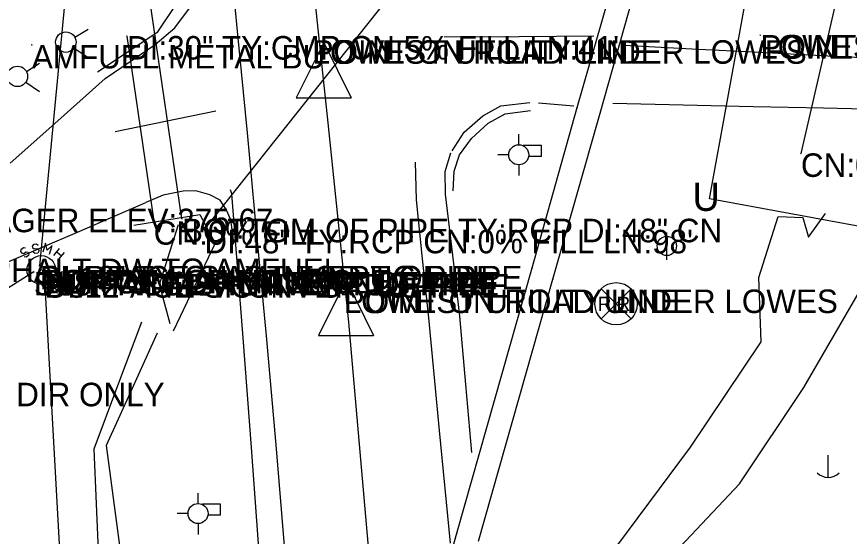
# Model space of a CAD drawing. Extents: x 929765 to 934279, y 1533086 to 1541189.
# Drawn here: x 931934.2 to 932111.4, y 1537427.6 to 1537538.1 of the extents above; entities that cross this region are included whole.
import ezdxf

# ---------------------------------------------------------------- set-up
doc = ezdxf.new("R2010")
doc.units = 0
for name, color, linetype in [('Default', 7, 'Continuous'), ('S_CAL_CORNER', 7, 'Continuous'), ('S_CROSS_DRAIN', 7, 'Continuous'), ('S_CROSS_DRAIN_ANNOT', 7, 'Continuous'), ('S_CURB', 7, 'Continuous'), ('S_DITCHLINE', 7, 'Continuous'), ('S_DRG_PT_SYM', 7, 'Continuous'), ('S_DRIVEWAY', 7, 'Continuous'), ('S_EDGE_CONCRETE', 7, 'Continuous'), ('S_EDGE_PAVEMENT', 7, 'Continuous'), ('S_ELECTRIC_UTILITIES_ANNOT', 7, 'Continuous'), ('S_HEADWALL', 7, 'Continuous'), ('S_HIST_HIGH_WATER_ANNOT', 7, 'Continuous'), ('S_MANHOLE_ANNOT', 7, 'Continuous'), ('S_MSC_PT_SYM', 7, 'Continuous'), ('S_PAVEMENT_CROWN', 7, 'Continuous'), ('S_RAILROAD', 7, 'Continuous'), ('S_SANITARY_SEWER', 7, 'Continuous'), ('S_SANITARY_SEWER_ANNOT', 7, 'Continuous'), ('S_SHOULDER', 7, 'Continuous'), ('S_STORM_SEWER', 7, 'Continuous'), ('S_STORM_SEWER_ANNOT', 7, 'Continuous'), ('S_SURVEY_TEXT_ANNOT', 7, 'Continuous'), ('S_UNDERGROUND_CABLE', 7, 'Continuous'), ('S_UTILITY_POLE', 7, 'Continuous'), ('S_UTL_PT_SYM', 7, 'Continuous'), ('S_WATER_UTILITIES', 7, 'Continuous')]:
    doc.layers.add(name, color=color, linetype=linetype)

msp = doc.modelspace()

# ---------------------------------------------------------------- linework, layer by layer
at = {"layer": 'S_CAL_CORNER'}
for p, q in [((931999.53, 1537532.6), (931993.65, 1537520.78)), ((931999.53, 1537532.6), (932005.34, 1537520.78)), ((931993.65, 1537520.78), (932005.34, 1537520.78)), ((932004.31, 1537482.11), (931998.43, 1537470.29)), ((932004.31, 1537482.11), (932010.12, 1537470.29)), ((931998.43, 1537470.29), (932010.12, 1537470.29))]:
    msp.add_line(p, q, dxfattribs=at)
at = {"layer": 'S_CROSS_DRAIN'}
for p, q in [((931974.13, 1537492.75), (932035.18, 1537569.61)), ((932110.43, 1537549.57), (932101.07, 1537509)), ((931957.67, 1537533.94), (931963.36, 1537494.58))]:
    msp.add_line(p, q, dxfattribs=at)
at = {"layer": 'S_CURB'}
for points in [[(931951.42, 1537526.31), (931964.23, 1537534.86), (931972.76, 1537547.6), (931973.29, 1537552.29), (931973.36, 1537555.14), (931972.31, 1537562.3), (931970.08, 1537579.27), (931967.84, 1537596.25), (931965.61, 1537613.23), (931963.38, 1537630.2), (931960.78, 1537646.56), (931958.18, 1537662.91), (931955.58, 1537679.26), (931952.98, 1537695.61), (931950.14, 1537711.26), (931947.3, 1537726.92), (931944.46, 1537742.57), (931941.62, 1537758.23)], [(932027.11, 1537501.01), (932027.27, 1537505.24), (932028.44, 1537508.67), (932030.95, 1537512.17), (932034.53, 1537515.45), (932038.11, 1537517.37), (932043.52, 1537518.14)], [(931980.38, 1537490.02), (931979.79, 1537494.9), (931978.77, 1537497.08), (931977.48, 1537499.06), (931975.31, 1537500.19), (931972.33, 1537501.01), (931969.61, 1537500.99), (931965.38, 1537500.09), (931961.69, 1537498.53)]]:
    msp.add_lwpolyline(points, dxfattribs=at)
at = {"layer": 'S_DITCHLINE'}
for points in [[(932085.78, 1537301.84), (932081.18, 1537319.05), (932076.57, 1537336.26), (932071.43, 1537351.35), (932066.29, 1537366.45), (932053.86, 1537378.37), (932049.5, 1537380.42), (932059.98, 1537382.88), (932059.48, 1537390.45), (932058.32, 1537398.79), (932058.33, 1537404.72), (932057.44, 1537410.6), (932057.14, 1537417.22), (932059.87, 1537422.73), (932068.73, 1537434.65), (932077.6, 1537446.56), (932085.12, 1537457.75), (932092.64, 1537468.94), (932092.11, 1537482.59), (932096.23, 1537495.57), (932101.45, 1537495.39), (932102.69, 1537491.18), (932106.29, 1537496.21)], [(932126.62, 1537258.44), (932108.91, 1537270.62), (932105.45, 1537284.68), (932101.98, 1537298.75), (932094.32, 1537317.71), (932086.66, 1537336.67), (932081.51, 1537352.24), (932076.37, 1537367.8), (932068.43, 1537383.73), (932067.92, 1537400.37), (932067.42, 1537417), (932077.7, 1537427.87), (932087.98, 1537438.73), (932101.66, 1537459.25), (932108.63, 1537471.21), (932115.61, 1537483.17), (932113.54, 1537495.88)], [(931960.73, 1537473.11), (931955.67, 1537459.62), (931950.61, 1537446.13), (931951.63, 1537422.85), (931946.42, 1537416.45), (931944.44, 1537403.55), (931942.46, 1537390.65), (931930.06, 1537380.86), (931917.67, 1537371.06), (931905.8, 1537349.22), (931891.3, 1537336.47)], [(931964.13, 1537470.78), (931958.69, 1537458.85), (931953.25, 1537446.93), (931956.11, 1537425.64), (931962.3, 1537423.93), (931964.69, 1537424.11), (931966.9, 1537401.27), (931969.1, 1537378.44), (931958.88, 1537373.67), (931949.96, 1537376.9), (931937.32, 1537372.75), (931924.68, 1537368.59), (931916.88, 1537353.63), (931909.08, 1537338.66), (931901.6, 1537326.5), (931894.11, 1537314.34), (931873.82, 1537300.85), (931853.53, 1537287.36), (931835.12, 1537272.97), (931824.41, 1537264.81), (931813.7, 1537256.65), (931802.99, 1537248.49), (931792.29, 1537240.33), (931772.04, 1537229.23)]]:
    msp.add_lwpolyline(points, dxfattribs=at)
at = {"layer": 'S_DRG_PT_SYM'}
for points in [[(931957.67, 1537533.94), (931957.67, 1537533.99), (931957.67, 1537533.94), (931957.62, 1537533.94), (931957.67, 1537533.94), (931957.67, 1537533.89), (931957.67, 1537533.94), (931957.72, 1537533.94)], [(932101.07, 1537509), (932101.07, 1537509.05), (932101.07, 1537509), (932101.02, 1537509), (932101.07, 1537509), (932101.07, 1537508.95), (932101.07, 1537509), (932101.12, 1537509)], [(931963.36, 1537494.58), (931963.36, 1537494.63), (931963.36, 1537494.58), (931963.31, 1537494.58), (931963.36, 1537494.58), (931963.36, 1537494.53), (931963.36, 1537494.58), (931963.41, 1537494.58)], [(931974.13, 1537492.75), (931974.13, 1537492.8), (931974.13, 1537492.75), (931974.08, 1537492.75), (931974.13, 1537492.75), (931974.13, 1537492.7), (931974.13, 1537492.75), (931974.18, 1537492.75)]]:
    msp.add_lwpolyline(points, dxfattribs=at)
at = {"layer": 'S_DRIVEWAY'}
for points in [[(931932.85, 1537506.93), (931942.95, 1537515.91), (931953.05, 1537524.89)], [(931932.55, 1537485.99), (931947.12, 1537492.26), (931961.69, 1537498.53)]]:
    msp.add_lwpolyline(points, dxfattribs=at)
at = {"layer": 'S_EDGE_CONCRETE'}
for points in [[(932026.88, 1537509.56), (932029.42, 1537513.53), (932033.42, 1537516.97), (932037.22, 1537519.12), (932043.39, 1537519.83)], [(931966.87, 1537472.8), (931964.6, 1537481.12), (931968.6, 1537493.89)]]:
    msp.add_lwpolyline(points, dxfattribs=at)
at = {"layer": 'S_EDGE_PAVEMENT'}
for points in [[(931999.26, 1537333.05), (931997.86, 1537345.98), (931996.59, 1537361.76), (931995.32, 1537377.53), (931993.34, 1537400.7), (931991.36, 1537423.88), (931989.38, 1537447.05), (931987.39, 1537470.22), (931985.33, 1537491.8), (931983.28, 1537513.38), (931981.22, 1537534.96), (931979.16, 1537556.54)], [(931953.05, 1537524.89), (931963.67, 1537532.14), (931967.87, 1537535.71), (931972.01, 1537541.26)], [(932045.23, 1537519.74), (932052.76, 1537519.09)], [(932061.04, 1537519.67), (932075.98, 1537519.33), (932090.91, 1537518.99), (932105.85, 1537518.66), (932120.78, 1537518.32), (932134.72, 1537517.68), (932148.65, 1537517.03), (932162.59, 1537516.39), (932176.52, 1537515.74), (932190.49, 1537514.88), (932204.46, 1537514.03), (932218.44, 1537513.17), (932232.41, 1537512.32), (932253.88, 1537511.23), (932275.34, 1537510.15), (932296.81, 1537509.07), (932318.28, 1537507.98), (932331.24, 1537507.41), (932344.21, 1537506.84), (932357.18, 1537506.27), (932370.14, 1537505.7)], [(932026.51, 1537426.11), (932024.2, 1537450.08), (932021.89, 1537474.04), (932020.58, 1537486.58), (932019.27, 1537499.11), (932019.09, 1537507.16)]]:
    msp.add_lwpolyline(points, dxfattribs=at)
at = {"layer": 'S_HEADWALL'}
msp.add_lwpolyline([(931959.16, 1537493.75), (931973.16, 1537495.99), (931976.41, 1537489.94), (931967.47, 1537471.24)], dxfattribs=at)
at = {"layer": 'S_MSC_PT_SYM'}
for points in [[(932092.43, 1537534.14), (932092.43, 1537534.19), (932092.43, 1537534.14), (932092.38, 1537534.14), (932092.43, 1537534.14), (932092.43, 1537534.09), (932092.43, 1537534.14), (932092.48, 1537534.14)], [(931997.16, 1537533.05), (931997.16, 1537533.1), (931997.16, 1537533.05), (931997.11, 1537533.05), (931997.16, 1537533.05), (931997.16, 1537533), (931997.16, 1537533.05), (931997.21, 1537533.05)], [(931937.44, 1537532.05), (931937.44, 1537532.1), (931937.44, 1537532.05), (931937.39, 1537532.05), (931937.44, 1537532.05), (931937.44, 1537532), (931937.44, 1537532.05), (931937.49, 1537532.05)], [(932053.49, 1537518.73), (932053.49, 1537518.78), (932053.49, 1537518.73), (932053.44, 1537518.73), (932053.49, 1537518.73), (932053.49, 1537518.68), (932053.49, 1537518.73), (932053.54, 1537518.73)], [(932058.32, 1537517.56), (932058.32, 1537517.61), (932058.32, 1537517.56), (932058.27, 1537517.56), (932058.32, 1537517.56), (932058.32, 1537517.51), (932058.32, 1537517.56), (932058.37, 1537517.56)], [(931939.08, 1537485.09), (931939.08, 1537485.14), (931939.08, 1537485.09), (931939.03, 1537485.09), (931939.08, 1537485.09), (931939.08, 1537485.04), (931939.08, 1537485.09), (931939.13, 1537485.09)], [(932043.89, 1537484.68), (932043.89, 1537484.73), (932043.89, 1537484.68), (932043.84, 1537484.68), (932043.89, 1537484.68), (932043.89, 1537484.63), (932043.89, 1537484.68), (932043.94, 1537484.68)], [(931937.87, 1537483.79), (931937.87, 1537483.84), (931937.87, 1537483.79), (931937.82, 1537483.79), (931937.87, 1537483.79), (931937.87, 1537483.74), (931937.87, 1537483.79), (931937.92, 1537483.79)], [(931940.09, 1537483.33), (931940.09, 1537483.38), (931940.09, 1537483.33), (931940.04, 1537483.33), (931940.09, 1537483.33), (931940.09, 1537483.28), (931940.09, 1537483.33), (931940.14, 1537483.33)], [(932048.31, 1537482.23), (932048.31, 1537482.28), (932048.31, 1537482.23), (932048.26, 1537482.23), (932048.31, 1537482.23), (932048.31, 1537482.18), (932048.31, 1537482.23), (932048.36, 1537482.23)], [(932003.8, 1537480.06), (932003.8, 1537480.11), (932003.8, 1537480.06), (932003.75, 1537480.06), (932003.8, 1537480.06), (932003.8, 1537480.01), (932003.8, 1537480.06), (932003.85, 1537480.06)], [(932027.87, 1537428.26), (932027.87, 1537428.31), (932027.87, 1537428.26), (932027.82, 1537428.26), (932027.87, 1537428.26), (932027.87, 1537428.21), (932027.87, 1537428.26), (932027.92, 1537428.26)]]:
    msp.add_lwpolyline(points, dxfattribs=at)
at = {"layer": 'S_PAVEMENT_CROWN'}
for points in [[(932013.1, 1537379.23), (932011.05, 1537402.7), (932008.99, 1537426.17), (932006.94, 1537449.63), (932004.88, 1537473.1), (932002.67, 1537494.31), (932000.45, 1537515.52), (931998.24, 1537536.73), (931996.02, 1537557.94)], [(932025.17, 1537533.78), (932041.09, 1537533.87), (932057.01, 1537533.96)], [(932063.43, 1537531.97), (932077.89, 1537531.23), (932092.36, 1537530.49), (932106.82, 1537529.75), (932121.29, 1537529.01), (932135.07, 1537528.19), (932148.84, 1537527.38), (932162.62, 1537526.56), (932176.4, 1537525.75), (932191.1, 1537524.87), (932205.8, 1537523.99), (932220.5, 1537523.11), (932235.2, 1537522.24), (932255.86, 1537521.16), (932276.51, 1537520.09), (932297.17, 1537519.01), (932317.82, 1537517.94), (932331.13, 1537517.43), (932344.43, 1537516.92), (932357.74, 1537516.42), (932371.04, 1537515.91)], [(931976.59, 1537517.96), (931955.18, 1537513.56)]]:
    msp.add_lwpolyline(points, dxfattribs=at)
at = {"layer": 'S_RAILROAD'}
for p, q in [((932053.49, 1537518.73), (932069.38, 1537574.33)), ((932058.32, 1537517.56), (932073.74, 1537571.91)), ((932043.89, 1537484.68), (932053.49, 1537518.73)), ((932048.31, 1537482.23), (932058.32, 1537517.56)), ((932041.03, 1537510.81), (932041.03, 1537513.06)), ((932045.84, 1537510.65), (932041.96, 1537510.65)), ((932045.84, 1537508.33), (932045.84, 1537510.65)), ((932038.94, 1537508.68), (932036.61, 1537508.68)), ((932045.84, 1537508.33), (932043.12, 1537508.33)), ((932041.11, 1537504.26), (932041.11, 1537506.58)), ((932027.87, 1537428.26), (932043.89, 1537484.68)), ((932032.49, 1537426.55), (932048.31, 1537482.23)), ((931972.79, 1537434.55), (931972.79, 1537436.8)), ((931977.6, 1537434.4), (931973.72, 1537434.4)), ((931977.6, 1537432.07), (931977.6, 1537434.4)), ((931970.7, 1537432.42), (931968.38, 1537432.42)), ((931977.6, 1537432.07), (931974.89, 1537432.07)), ((931972.87, 1537428), (931972.87, 1537430.33)), ((932013.4, 1537376.69), (932027.87, 1537428.26))]:
    msp.add_line(p, q, dxfattribs=at)
for points in [[(932058.57, 1537480.2), (932061.75, 1537477.02), (932058.57, 1537473.83)], [(932064.93, 1537480.2), (932061.75, 1537477.02), (932064.93, 1537473.83)]]:
    msp.add_lwpolyline(points, dxfattribs=at)
for centre, radius in [((932041.03, 1537508.7), 2.13), ((932061.75, 1537477.02), 4.5), ((931972.79, 1537432.44), 2.13)]:
    msp.add_circle(centre, radius, dxfattribs=at)
at = {"layer": 'S_SANITARY_SEWER'}
for p, q in [((931946.28, 1537561.11), (931939.08, 1537485.09)), ((931935.11, 1537488.52), (931935.03, 1537488.14)), ((931935.03, 1537488.14), (931935.23, 1537487.87)), ((931935.65, 1537488.91), (931935.11, 1537488.52)), ((931936.08, 1537488.83), (931935.65, 1537488.91)), ((931935.65, 1537487.75), (931936.2, 1537488.1)), ((931936.2, 1537488.1), (931936.66, 1537488.02)), ((931936.66, 1537488.02), (931936.82, 1537487.75)), ((931942.09, 1537487.28), (931943.33, 1537488.76)), ((931942.74, 1537488.06), (931943.71, 1537487.25)), ((931944.29, 1537487.94), (931943.05, 1537486.47)), ((931935.23, 1537487.87), (931935.65, 1537487.75)), ((931936.2, 1537486.94), (931935.81, 1537487.01)), ((931936.74, 1537487.32), (931936.2, 1537486.94)), ((931936.82, 1537487.75), (931936.74, 1537487.32)), ((931937.87, 1537483.79), (931900.29, 1537460.24)), ((931950.77, 1537292.06), (931940.09, 1537483.33))]:
    msp.add_line(p, q, dxfattribs=at)
for points in [[(931938.75, 1537489.45), (931938.4, 1537489.73), (931937.75, 1537489.65), (931937.51, 1537489.3), (931937.55, 1537488.99), (931937.9, 1537488.68), (931938.52, 1537488.8), (931938.91, 1537488.49), (931938.95, 1537488.18), (931938.68, 1537487.79), (931938.06, 1537487.71), (931937.71, 1537487.98)], [(931941.19, 1537487.59), (931941.74, 1537489.45), (931940.69, 1537488.45), (931940.3, 1537489.88), (931939.76, 1537488.02)]]:
    msp.add_lwpolyline(points, dxfattribs=at)
msp.add_circle((931939.44, 1537484.22), 3.05, dxfattribs=at)
at = {"layer": 'S_SHOULDER'}
for points in [[(932031.07, 1537445.4), (932029.8, 1537459.9), (932028.52, 1537474.39), (932026.98, 1537487.36), (932025.44, 1537500.33), (932025.4, 1537505.13), (932026.6, 1537509.09)], [(931992.49, 1537324.27), (931991.71, 1537337.31), (931990.93, 1537350.35), (931990.15, 1537363.39), (931989.37, 1537376.43), (931987.64, 1537399.77), (931985.9, 1537423.12), (931984.16, 1537446.46), (931982.42, 1537469.81), (931981.22, 1537485.1), (931980.01, 1537500.39), (931979.72, 1537501.28)]]:
    msp.add_lwpolyline(points, dxfattribs=at)
at = {"layer": 'S_STORM_SEWER'}
msp.add_line((931969.37, 1537495.1), (931941.79, 1537683.51), dxfattribs=at)
at = {"layer": 'S_UNDERGROUND_CABLE'}
for p, q in [((932081.62, 1537499.31), (932094.03, 1537567.82)), ((932135.91, 1537489.36), (932081.62, 1537499.31))]:
    msp.add_line(p, q, dxfattribs=at)
at = {"layer": 'S_UTILITY_POLE'}
for p, q in [((932072.53, 1537486.38), (932072.53, 1537492.17)), ((931943.79, 1537483.93), (931943.79, 1537479.2)), ((931944.47, 1537484.24), (931944.47, 1537479.51)), ((932106.81, 1537444.84), (932106.81, 1537440.11))]:
    msp.add_line(p, q, dxfattribs=at)
msp.add_circle((932072.53, 1537489.31), 2.05, dxfattribs=at)
for centre in [(931943.85, 1537482.63), (931944.53, 1537482.94), (932106.87, 1537443.54)]:
    msp.add_arc(centre, 3.41, 226.3972, 313.6028, dxfattribs=at)
at = {"layer": 'S_UTL_PT_SYM'}
for points in [[(932092.43, 1537534.14), (932092.43, 1537534.19), (932092.43, 1537534.14), (932092.38, 1537534.14), (932092.43, 1537534.14), (932092.43, 1537534.09), (932092.43, 1537534.14), (932092.48, 1537534.14)], [(931997.16, 1537533.05), (931997.16, 1537533.1), (931997.16, 1537533.05), (931997.11, 1537533.05), (931997.16, 1537533.05), (931997.16, 1537533), (931997.16, 1537533.05), (931997.21, 1537533.05)], [(931969.37, 1537495.1), (931969.37, 1537495.15), (931969.37, 1537495.1), (931969.32, 1537495.1), (931969.37, 1537495.1), (931969.37, 1537495.05), (931969.37, 1537495.1), (931969.42, 1537495.1)], [(931939.08, 1537485.09), (931939.08, 1537485.14), (931939.08, 1537485.09), (931939.03, 1537485.09), (931939.08, 1537485.09), (931939.08, 1537485.04), (931939.08, 1537485.09), (931939.13, 1537485.09)], [(931937.87, 1537483.79), (931937.87, 1537483.84), (931937.87, 1537483.79), (931937.82, 1537483.79), (931937.87, 1537483.79), (931937.87, 1537483.74), (931937.87, 1537483.79), (931937.92, 1537483.79)], [(931939.44, 1537484.22), (931939.44, 1537484.27), (931939.44, 1537484.22), (931939.39, 1537484.22), (931939.44, 1537484.22), (931939.44, 1537484.17), (931939.44, 1537484.22), (931939.49, 1537484.22)], [(931940.09, 1537483.33), (931940.09, 1537483.38), (931940.09, 1537483.33), (931940.04, 1537483.33), (931940.09, 1537483.33), (931940.09, 1537483.28), (931940.09, 1537483.33), (931940.14, 1537483.33)], [(932003.8, 1537480.06), (932003.8, 1537480.11), (932003.8, 1537480.06), (932003.75, 1537480.06), (932003.8, 1537480.06), (932003.8, 1537480.01), (932003.8, 1537480.06), (932003.85, 1537480.06)]]:
    msp.add_lwpolyline(points, dxfattribs=at)
at = {"layer": 'S_WATER_UTILITIES'}
for p, q in [((931946.57, 1537533.69), (931949.4, 1537535.42)), ((931946.45, 1537531.38), (931949.36, 1537529.46)), ((931936.26, 1537526.42), (931939.08, 1537528.15)), ((931936.14, 1537524.11), (931939.05, 1537522.18))]:
    msp.add_line(p, q, dxfattribs=at)
for centre in [(931944.67, 1537532.64), (931934.36, 1537525.36)]:
    msp.add_circle(centre, 2.18, dxfattribs=at)

# ---------------------------------------------------------------- texts
at = {"layer": 'Default'}
msp.add_text('U', height=6, rotation=360, dxfattribs=at).set_placement((932078, 1537496.77))
at = {"layer": 'S_CROSS_DRAIN_ANNOT'}
for s, p in [('DI:30" TY:CMP CN:5% FILL LN:41\'', (931957.67, 1537528.94)), ('CN:0% FILL', (932101.07, 1537504)), ('CN:0% FILL', (931963.36, 1537489.58)), ('DI:48" TY:RCP CN:0% FILL LN:98\'', (931974.13, 1537487.75))]:
    msp.add_text(s, height=5, dxfattribs=at).set_placement(p)
at = {"layer": 'S_ELECTRIC_UTILITIES_ANNOT'}
for p in [(932092.43, 1537529.14), (931997.16, 1537528.05), (932003.8, 1537475.06)]:
    msp.add_text('LOWEST UTILITY LINE', height=5, dxfattribs=at).set_placement(p)
at = {"layer": 'S_HIST_HIGH_WATER_ANNOT'}
msp.add_text('PER AMFUEL MANAGER ELEV:275.67', height=5, dxfattribs=at).set_placement((931869.17, 1537492.24))
at = {"layer": 'S_MANHOLE_ANNOT'}
msp.add_text('BOTTOM OF MANHOLE', height=5, dxfattribs=at).set_placement((931939.44, 1537479.22))
at = {"layer": 'S_RAILROAD'}
msp.add_text('R R', height=3, rotation=360, dxfattribs=at).set_placement((932057.84, 1537475.52))
msp.add_text('R R', height=3, rotation=360, dxfattribs=at).set_placement((932057.84, 1537475.52))
at = {"layer": 'S_SANITARY_SEWER_ANNOT'}
for s, p in [('DI:12" TY:CLAY INVERT OF PIPE', (931939.08, 1537480.09)), ('DI:8" TY:CLAY INVERT OF PIPE', (931937.87, 1537478.79)), ('TOP OF MANHOLE', (931939.44, 1537479.22)), ('DI:12" TY:PVC INVERT OF PIPE', (931940.09, 1537478.33)), ('SURFACE DIR ONLY', (931900.29, 1537455.24))]:
    msp.add_text(s, height=5, dxfattribs=at).set_placement(p)
at = {"layer": 'S_STORM_SEWER_ANNOT'}
msp.add_text('BOTTOM OF PIPE TY:RCP DI:48" CN', height=5, dxfattribs=at).set_placement((931969.37, 1537490.1))
at = {"layer": 'S_SURVEY_TEXT_ANNOT'}
for s, p in [('POINT ON ROAD UNDER LOWES', (932092.43, 1537529.14)), ('POINT ON ROAD UNDER LOWES', (931997.16, 1537528.05)), ('AMFUEL METAL BU', (931937.44, 1537527.05)), ('ASPHALT DW TO AMFUEL', (931919.64, 1537481.65)), ('SURFACE SHOT FOR UG PIPE', (931939.08, 1537480.09)), ('SURFACE SHOT FOR UG PIPE', (931937.87, 1537478.79)), ('SURFACE SHOT FOR UG PIPE', (931940.09, 1537478.33)), ('POINT ON ROAD UNDER LOWES', (932003.8, 1537475.06))]:
    msp.add_text(s, height=5, dxfattribs=at).set_placement(p)

doc.saveas('drawing.dxf')
